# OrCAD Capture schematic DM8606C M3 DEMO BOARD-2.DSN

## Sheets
1 (1)MAIN_TP_FIBER: size A3; title: DM8606C M3 MODE DEMO BOARD; rev: 2.0; company: Davicom Semiconductor Inc; note: DM8606C_MAIN
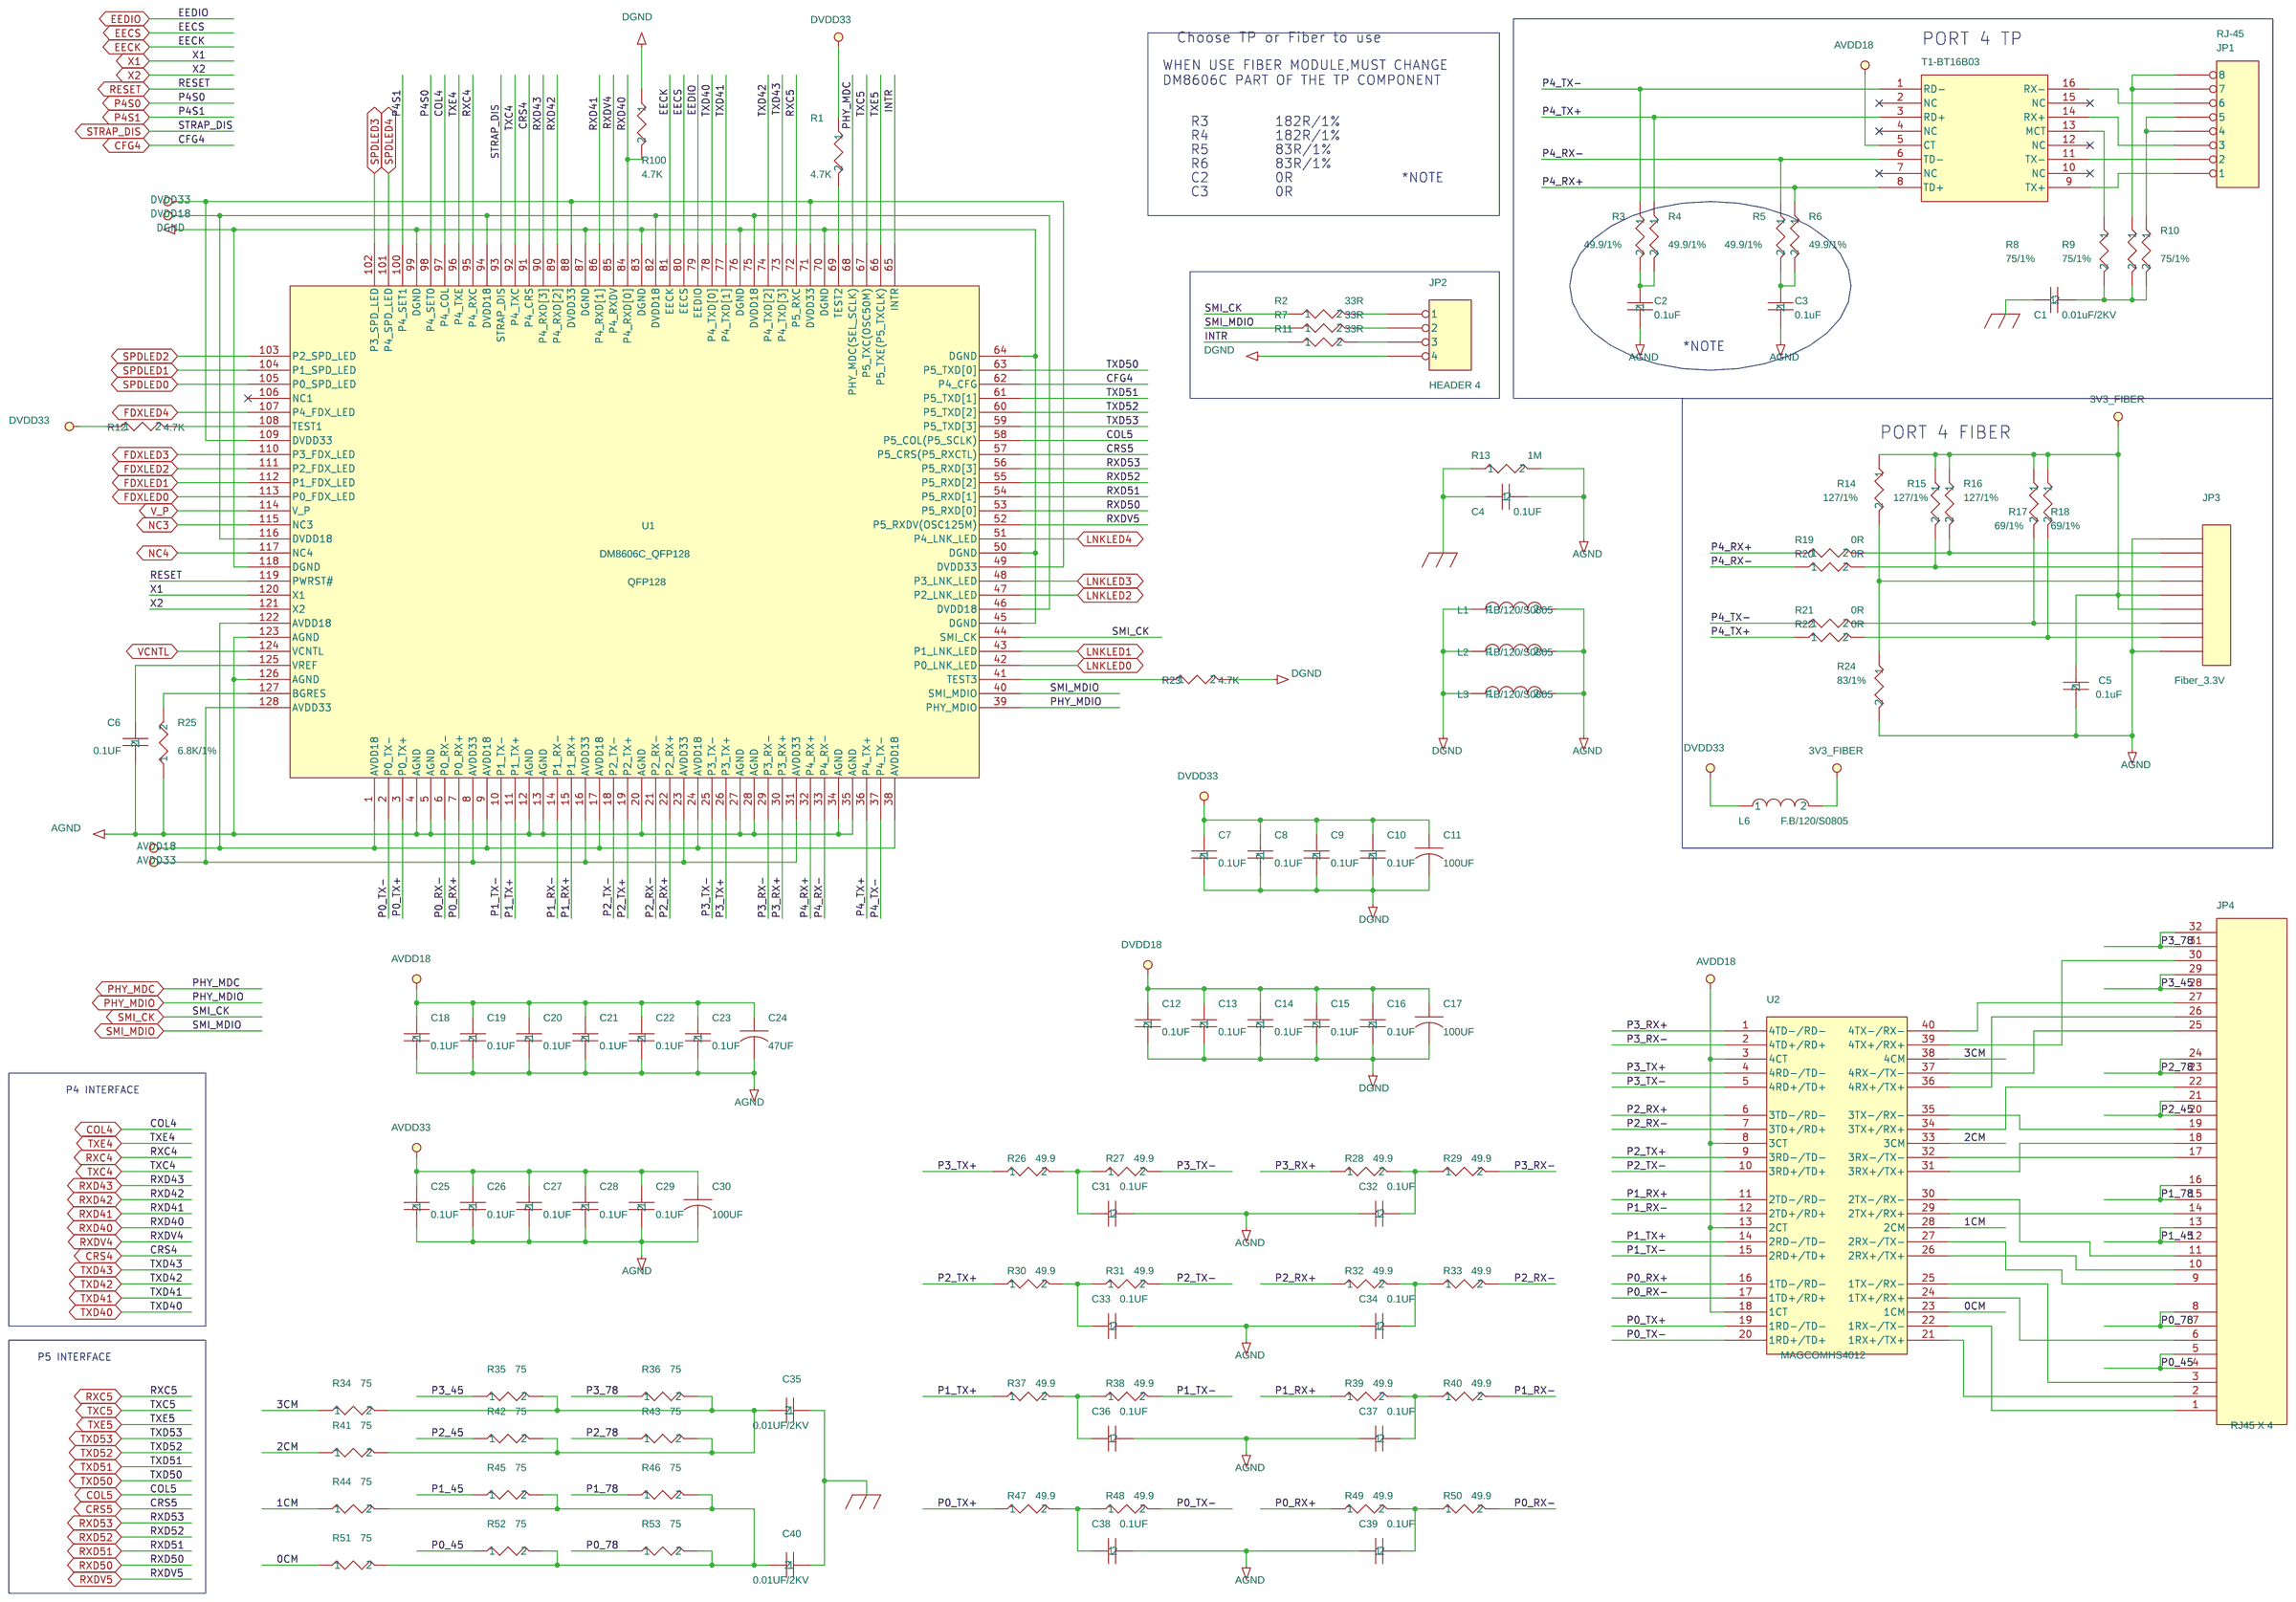
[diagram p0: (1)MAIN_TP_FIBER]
2 (2)RPOWER_STRAP_RST_XTAL_EPRROM: size A3; company: Davicom Semicondutor Inc; note: RPOWER_STRAP_RST_XTAL_EPRROM
3 (3)HISTORY: note: HISTORY
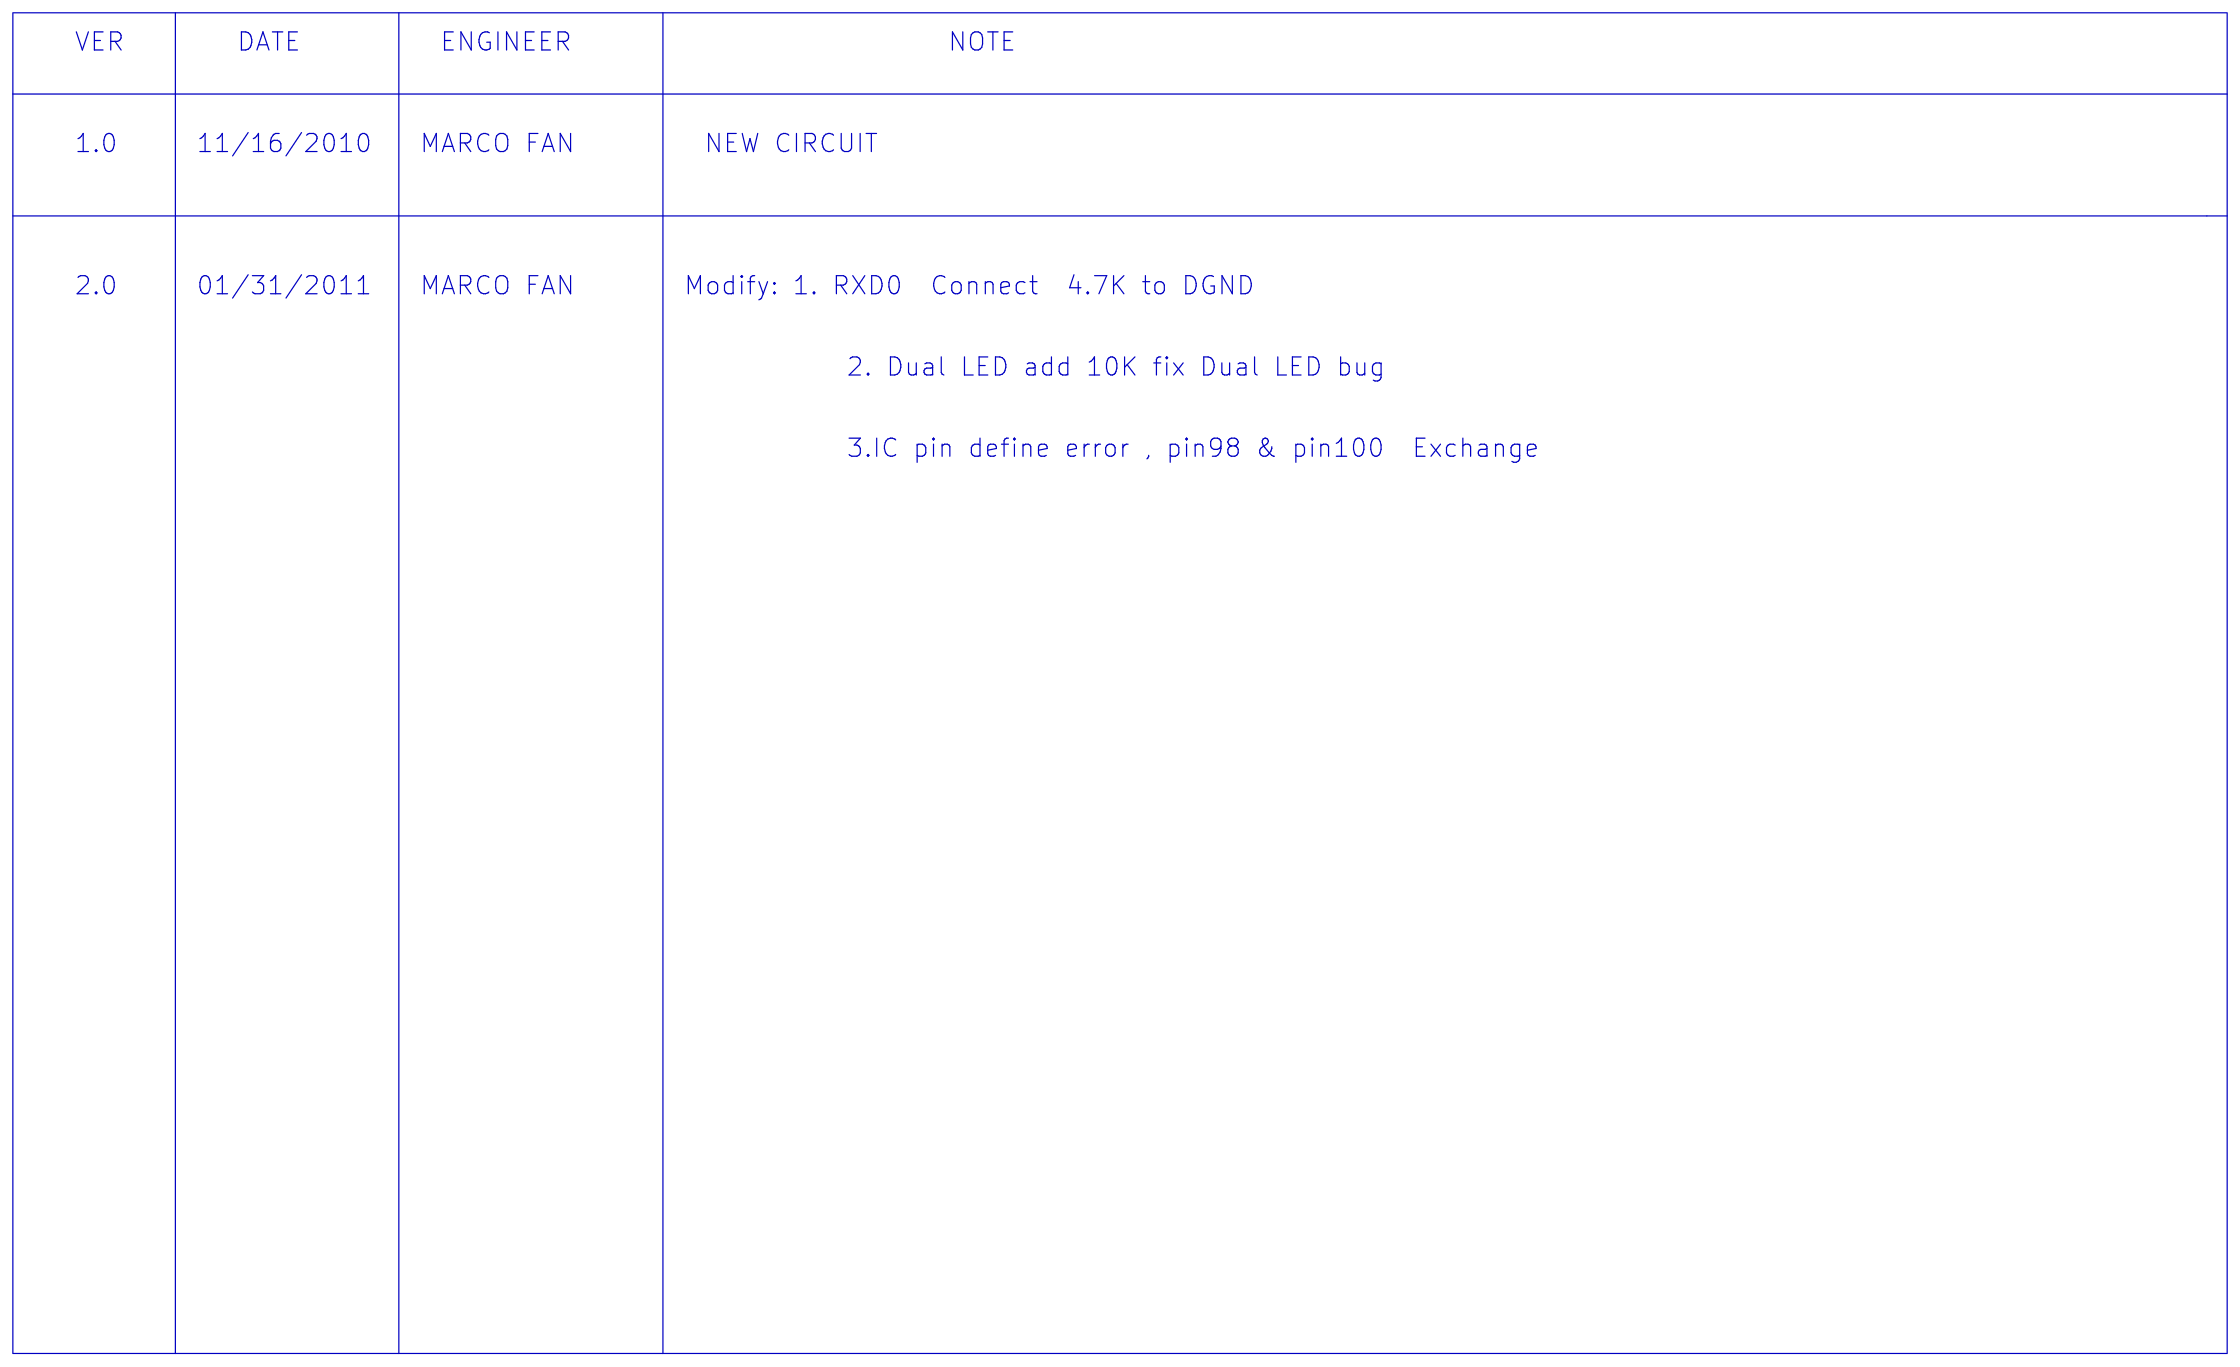
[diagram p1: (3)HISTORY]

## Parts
sheet (1)MAIN_TP_FIBER
C1  0.01uF/2KV  [CAP5MM]
C2  0.1uF  [C0603]
C3  0.1uF  [C0603]
C4  0.1UF  [C0603]
C5  0.1uF  [C0603]
C6  0.1UF  [C0603]
C7  0.1UF  [C0603]
C8  0.1UF  [C0603]
C9  0.1UF  [C0603]
C10  0.1UF  [C0603]
C11  100UF  [EC-MR05-2.5]
C12  0.1UF  [C0603]
C13  0.1UF  [C0603]
C14  0.1UF  [C0603]
C15  0.1UF  [C0603]
C16  0.1UF  [C0603]
C17  100UF  [EC-MR05-2.5]
C18  0.1UF  [C0603]
C19  0.1UF  [C0603]
C20  0.1UF  [C0603]
C21  0.1UF  [C0603]
C22  0.1UF  [C0603]
C23  0.1UF  [C0603]
C24  47UF  [EC-MR05-2.5]
C25  0.1UF  [C0603]
C26  0.1UF  [C0603]
C27  0.1UF  [C0603]
C28  0.1UF  [C0603]
C29  0.1UF  [C0603]
C30  100UF  [EC-MR05-2.5]
C31  0.1UF  [C0603]
C32  0.1UF  [C0603]
C33  0.1UF  [C0603]
C34  0.1UF  [C0603]
C35  0.01UF/2KV  [CAP5MM]
C36  0.1UF  [C0603]
C37  0.1UF  [C0603]
C38  0.1UF  [C0603]
C39  0.1UF  [C0603]
C40  0.01UF/2KV  [CAP5MM]
JP1  RJ-45  [RJ45]
JP2  HEADER 4  [CON4_SIP-2.54]
JP3  Fiber_3.3V  [FIBER]
JP4  RJ45 X 4  [YCLPTC1411-31_RJ45-4P]
L1  F.B/120/S0805  [R0805]
L2  F.B/120/S0805  [R0805]
L3  F.B/120/S0805  [R0805]
L6  F.B/120/S0805  [R0805]
R1  4.7K  [R0603]
R2  33R  [R0603]
R3  49.9/1%  [R0603]
R4  49.9/1%  [R0603]
R5  49.9/1%  [R0603]
R6  49.9/1%  [R0603]
R7  33R  [R0603]
R8  75/1%  [R0603]
R9  75/1%  [R0603]
R10  75/1%  [R0603]
R11  33R  [R0603]
R12  4.7K  [R0603]
R13  1M  [R0603]
R14  127/1%  [R0603]
R15  127/1%  [R0603]
R16  127/1%  [R0603]
R17  69/1%  [R0603]
R18  69/1%  [R0603]
R19  0R  [R0603]
R20  0R  [R0603]
R21  0R  [R0603]
R22  0R  [R0603]
R23  4.7K  [R0603]
R24  83/1%  [R0603]
R25  6.8K/1%  [R0603]
R26  49.9  [R0603]
R27  49.9  [R0603]
R28  49.9  [R0603]
R29  49.9  [R0603]
R30  49.9  [R0603]
R31  49.9  [R0603]
R32  49.9  [R0603]
R33  49.9  [R0603]
R34  75  [R0603]
R35  75  [R0603]
R36  75  [R0603]
R37  49.9  [R0603]
R38  49.9  [R0603]
R39  49.9  [R0603]
R40  49.9  [R0603]
R41  75  [R0603]
R42  75  [R0603]
R43  75  [R0603]
R44  75  [R0603]
R45  75  [R0603]
R46  75  [R0603]
R47  49.9  [R0603]
R48  49.9  [R0603]
R49  49.9  [R0603]
R50  49.9  [R0603]
R51  75  [R0603]
R52  75  [R0603]
R53  75  [R0603]
R100  4.7K
T1-BT16B03  MACOM9024  [PH163539]
U1  DM8606C_QFP128  [DM8606C-LQFP]
U2  MAGCOMHS4012  [MAGCOMHS4012_TR40-2916-1.27]
sheet (2)RPOWER_STRAP_RST_XTAL_EPRROM
C41  20P  [C0603]
C42  20P  [C0603]
C43  100UF/16V  [EC-MR05-2.5]
C44  100UF/10V  [EC-MR05-2.5]
C45  0.1UF  [C0603]
C46  0.1UF  [C0603]
C47  100UF/10V  [EC-MR05-2.5]
C48  0.1UF  [C0603]
C53  0.1uF  [C0603]
C54  100uF/10V  [EC-MR05-2.5]
C55  0.1uF  [C0603]
C56  100uF/10V  [EC-MR05-2.5]
C57  1uF  [C0603]
C58  0.1UF  [C0603]
C59  10UF/10V  [EC-MR05-2.5]
D2  DUAL LED  [2DIP-LED]
D3  DUAL LED  [2DIP-LED]
D4  DUAL LED  [2DIP-LED]
D5  DUAL LED  [2DIP-LED]
D6  DUAL LED  [2DIP-LED]
D7  DUAL LED  [2DIP-LED]
D8  DUAL LED  [2DIP-LED]
D9  DUAL LED  [2DIP-LED]
D10  DUAL LED  [2DIP-LED]
D11  DUAL LED  [2DIP-LED]
D12  DUAL LED  [2DIP-LED]
D13  DUAL LED  [2DIP-LED]
D14  DUAL LED  [2DIP-LED]
D15  LED  [2DIP-LED]
D16  LED  [2DIP-LED]
J1  CON3_0  [CON3_SIP3-2.54]
J2  CON3_0  [CON3_SIP3-2.54]
J3  CON3_0  [CON3_SIP3-2.54]
J4  CON3_0  [CON3_SIP3-2.54]
J5  CON3_0  [CON3_SIP3-2.54]
J6  CON3_0  [CON3_SIP3-2.54]
J7  CON3_0  [CON3_SIP3-2.54]
J8  CON3_0  [CON3_SIP3-2.54]
J9  JUMPER  [SIP2-2.54]
J10  CON3_0  [CON3_SIP3-2.54]
J11  CON3_0  [CON3_SIP3-2.54]
J12  CON3_0  [CON3_SIP3-2.54]
J13  CON3_0  [CON3_SIP3-2.54]
J14  CON3_0  [CON3_SIP3-2.54]
J15  CON3_0  [CON3_SIP3-2.54]
J16  CON3_0  [CON3_SIP3-2.54]
J17  CON3_0  [CON3_SIP3-2.54]
JP5  HEADER_16X2  [CON16X2-2.54A]
JP6  HEADER_16X2  [CON16X2-2.54A]
L4  F.B/120/S0805  [R0805]
L5  F.B/120/SO805  [R0805]
P1  DC-JACK  [DCJACK]
Q1  2SB1386  [SOT89]
R54  330  [R0603]
R55  330  [R0603]
R56  330  [R0603]
R57  10K  [R0603]
R58  330  [R0603]
R59  10K  [R0603]
R60  330  [R0603]
R61  10K  [R0603]
R62  330  [R0603]
R63  330  [R0603]
R64  10K  [R0603]
R65  330  [R0603]
R66  147  [R0603]
R67  10K  [R0603]
R68  330  [R0603]
R69  10K  [R0603]
R70  330  [R0603]
R71  10K  [R0603]
R72  330  [R0603]
R73  10K  [R0603]
R74  330  [R0603]
R75  10K  [R0603]
R76  10K  [R0603]
R77  10K  [R0603]
R78  330  [R0603]
R79  10K  [R0603]
R80  330  [R0603]
R81  10K  [R0603]
R82  330  [R0603]
R83  10K  [R0603]
R84  330  [R0603]
R85  10K  [R0603]
R86  NC/10K  [R0603]
R87  4.7K  [R0603]
R88  NC/10K  [R0603]
R90  4.7K  [R0603]
R92  4.7K/NC  [R0603]
R93  4.7K  [R0603]
R95  NC/4.7K  [R0603]
R96  NC/4.7K  [R0603]
R97  NC/4.7K  [R0603]
R98  NC/4.7K  [R0603]
R99  NC/4.7K  [R0603]
SW1  RESET_BUTTON  [SW-1102]
U3  RT9172  [SOT252]
U4  AP1117-1.8V  [SOT223]
U5  93C66/DIP8  [93C46]
U6  RESET_IC(AP1701DW)  [SOT23-213]
X1  25MHZ  [25MHZ/49US]

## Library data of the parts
C1 = CAP_NP_23: 1ST PART FIELD: CE
C2 C57 = CAP_NP_4
C3 C42 = CAP_NP_8
C4 = CAP_NP_13
C5 = CAP_NP_31
C6 = CAP_NP_28
C7 = CAP_NP_10
C8 = CAP_NP_33
C9 = CAP_NP_21
C10 C53 = CAP_NP_7
C11 C17 C30 = CAP
C12 = CAP_NP_32
C13 = CAP_NP_19
C14 C48 = CAP_NP_5
C15 = CAP_NP_30
C16 = CAP_NP_18
C18 = CAP_NP_12
C19 = CAP_NP_34
C20 = CAP_NP_24
C21 = CAP_NP_9
C22 = CAP_NP_17
C23 C46 = CAP_NP_1
C24 C47 C54 C56 = C
C25 = CAP_NP_14
C26 = CAP_NP_27
C27 C41 = CAP_NP_2
C28 C58 = CAP_NP
C29 = CAP_NP_25
C31 = CAP_NP_29
C32 = CAP_NP_16
C33 = CAP_NP_35
C34 = CAP_NP_20
C35 = CAP_NP_22: 1ST PART FIELD: C0603
C36 = CAP_NP_15
C37 C45 = CAP_NP_3
C38 = CAP_NP_26
C39 C55 = CAP_NP_6
C40 = CAP_NP_11: 1ST PART FIELD: C0603
JP1 = HEADER_8: 1ST PART FIELD: RJ8-45
JP2 = HEADER_8_0
JP3 = CON9
JP4 = RJ45X4_4
L1 = INDUCTOR_2
L2 L4 = INDUCTOR
L3 = INDUCTOR_3
L5 L6 = INDUCTOR_1
R1 R90 = RESISTOR_1
R2 = R_41
R3 = R_20
R4 = R_26
R5 = R_39
R6 = R_48
R7 = R_19
R8 = R_47
R9 = R_27
R10 R85 = R_15
R11 R93 = R_5
R12 R92 = RESISTOR
R13 = R_33
R14 R73 = R_6
R15 = R_25
R16 = R_22
R17 = R_32
R18 = R_21
R19 = R_43
R20 = R_18
R21 R64 = R_4
R22 = R_31
R23 R99 = RESISTOR_2
R24 R67 = R_8
R25 R95 = RESISTOR_3
R26 = R_24
R27 = R_46
R28 = R_30
R29 = R_38
R30 = R_35
R31 = R_37
R32 = R_44
R33 R79 = R_10
R34 = R_16
R35 = R_17
R36 R59 = R_14
R37 R69 = R_13
R38 R86 = R_9
R39 = R_49
R40 = R_42
R41 = R_34
R42 = R_36
R43 R66 = R_2
R44 = R_28
R45 R62 = R
R46 = R_40
R47 R88 = R_11
R48 R76 = R_7
R49 = R_45
R50 R58 = R_1
R51 = R_23
R52 R61 = R_12
R53 = R_29
R71 R100 = R_3
T1-BT16B03 = ETHERNET_TRANSFORMER_0
U1 = 9102A_15: 1ST PART FIELD: QFP128
U2 = MIM_9: 1ST PART FIELD: YCL0303
C43 = CAPACITOR_POL: 1ST PART FIELD: EC-MR05-2
C44 = CAPACITOR_POL_1: 1ST PART FIELD: EC-MR05-2
C59 = CAPACITOR_POL_2: 1ST PART FIELD: EC-MR05-2
D2-D14 = LED_0
D15 D16 = LED
J1-J8 J10-J17 = CON3_0
J9 = JUMPER
JP5 = HEADER_16X2_1
JP6 = HEADER_16X2
P1 = PJACK21_0: 3RD PART FIELD: DCIN; Package Type: 1; Part Number: 119211-005; Schematic Symbol: SIP3P
Q1 = BJT-PNP_0
R54-R57 R60 R63 R65 R68 R70 R72 R74 R77 R78 R80-R84 = resistor
R75 = RESISTOR_5
R87 = RESISTOR_6
R96 = RESISTOR_4
R97 = RESISTOR_7
R98 = RESISTOR_8
SW1 = SW_PUSHBUTTON: Package Type: 1
U3 = RT9172-25CM,TO-263_1
U4 = 1117-3_2.3
U5 = 9346_0
U6 = CON3_1
X1 = CRYSTAL

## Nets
3V3_FIBER: C5.1 JP3.5 JP3.6 L6.2 R14.1 R15.1 R16.1 R17.1 R18.1
5V: C43.1 C45.2 JP5.29 JP5.31 JP6.29 JP6.31 P1.1 U3.3(VIN)
AGND: C2.2 C3.2 C4.2 C5.2 C6.2 C18.2 C19.2 C20.2 C21.2 C22.2 C23.2 C24.2 C25.2 C26.2 C27.2 C28.2 C29.2 C30.2 C31.2 C32.1 C33.2 C34.1 C36.2 C37.1 C38.2 C39.1 C41.2 C42.2 C47.2 C48.2 C53.2 C54.2 C57.2 JP3.1 JP3.9 L1.2 L2.2 L3.2 R13.2 R24.2 R25.1 R66.2 U1.4(AGND) U1.5(AGND) U1.12(AGND) U1.13(AGND) U1.20(AGND) U1.27(AGND) U1.28(AGND) U1.34(AGND) U1.35(AGND) U1.123(AGND) U1.126(AGND)
AVDD18: C18.1 C19.1 C20.1 C21.1 C22.1 C23.1 C24.1 C53.1 C54.1 L5.1 Q1.C(COLLECTOR) R62.1 T1-BT16B03.5(CT) U1.1(AVDD18) U1.9(AVDD18) U1.17(AVDD18) U1.24(AVDD18) U1.38(AVDD18) U1.122(AVDD18) U2.3(4CT) U2.8(3CT) U2.13(2CT) U2.18(1CT) U4.2(OUT) U4.4(OUT)
AVDD33: C25.1 C26.1 C27.1 C28.1 C29.1 C30.1 C47.1 C48.1 L4.2 Q1.E(EMITTER) U1.8(AVDD33) U1.16(AVDD33) U1.23(AVDD33) U1.31(AVDD33) U1.128(AVDD33) U4.3(IN)
DGND: C7.2 C8.2 C9.2 C10.2 C11.2 C12.2 C13.2 C14.2 C15.2 C16.2 C17.2 C43.2 C44.2 C45.1 C46.2 C55.2 C56.2 C58.2 C59.2 J1.1 J2.1 J3.1 J4.1 J5.1 J6.1 J7.1 J8.1 J10.1 J11.1 J12.1 J13.1 J14.1 J15.1 J16.1 J17.1 JP2.4 JP5.23 JP5.25 JP5.27 JP6.23 JP6.25 JP6.27 L1.1 L2.1 L3.1 P1.2 P1.3 R23.2 R100.1 SW1.2 U1.45(DGND) U1.50(DGND) U1.64(DGND) U1.70(DGND) U1.76(DGND) U1.83(DGND) U1.87(DGND) U1.99(DGND) U1.118(DGND) U3.1(G) U5.5(GND) U6.1
DVDD18: C12.1 C13.1 C14.1 C15.1 C16.1 C17.1 C55.1 C56.1 L5.2 U1.46(DVDD18) U1.75(DVDD18) U1.82(DVDD18) U1.94(DVDD18) U1.116(DVDD18)
DVDD33: C7.1 C8.1 C9.1 C10.1 C11.1 C44.1 C46.1 C58.1 J1.3 J2.3 J3.3 J4.3 J5.3 J6.3 J7.3 J8.3 J10.3 J11.3 J12.3 J13.3 J14.3 J15.3 J16.3 J17.3 JP5.17 JP5.19 JP5.21 JP6.17 JP6.19 JP6.21 L4.1 L6.1 R1.1 R12.1 R54.2 R55.2 R76.2 R86.1 R88.1 R92.2 R95.2 R96.2 R97.2 R98.2 R99.2 U1.49(DVDD33) U1.71(DVDD33) U1.88(DVDD33) U1.109(DVDD33) U3.2(VOUT) U5.8(VCC) U6.3
GND_EARTH: C1.1 C4.1 C35.1 C40.1 R13.1
0CM: R51.1 U2.23(1CM)
1CM: R44.1 U2.28(2CM)
2CM: R41.1 U2.33(3CM)
3CM: R34.1 U2.38(4CM)
CFG4: R92.1 U1.62(P4_CFG)
COL4: JP5.14 U1.97(P4_COL)
COL5: JP6.14 U1.58(P5_COL(P5_SCLK))
CRS4: JP5.12 U1.91(P4_CRS)
CRS5: JP6.12 U1.57(P5_CRS(P5_RXCTL))
EECK: R98.1 U1.81(EECK) U5.2(SK)
EECS: J9.1 R97.1 U1.80(EECS)
EEDIO: R75.1 U1.79(EEDIO) U5.3(DI)
FDXLED0: D10.2(CATHODE) R77.1 U1.113(P0_FDX_LED)
FDXLED1: D11.2(CATHODE) R79.1 U1.112(P1_FDX_LED)
FDXLED2: D12.2(CATHODE) R81.1 U1.111(P2_FDX_LED)
FDXLED3: D13.2(CATHODE) R83.1 U1.110(P3_FDX_LED)
FDXLED4: D14.2(CATHODE) R85.1 U1.107(P4_FDX_LED)
INTR: R11.1 U1.65(INTR)
LNKLED0: D15.2(CATHODE) U1.42(P0_LNK_LED)
LNKLED1: D16.2(CATHODE) U1.43(P1_LNK_LED)
LNKLED2: D2.2(CATHODE) R57.1 U1.47(P2_LNK_LED)
LNKLED3: D3.2(CATHODE) R59.1 U1.48(P3_LNK_LED)
LNKLED4: D4.2(CATHODE) R61.1 U1.51(P4_LNK_LED)
NC3: R95.1 U1.115(NC3)
NC4: R96.1 U1.117(NC4)
P0_45: JP4.4 JP4.5 R52.1
P0_78: JP4.7 JP4.8 R53.1
P0_RX+: R49.1 U1.7(P0_RX+) U2.16(1TD-/RD-)
P0_RX-: R50.2 U1.6(P0_RX-) U2.17(1TD+/RD+)
P0_TX+: R47.1 U1.3(P0_TX+) U2.19(1RD-/TD-)
P0_TX-: R48.2 U1.2(P0_TX-) U2.20(1RD+/TD+)
P1_45: JP4.12 JP4.13 R45.1
P1_78: JP4.15 JP4.16 R46.1
P1_RX+: R39.1 U1.15(P1_RX+) U2.11(2TD-/RD-)
P1_RX-: R40.2 U1.14(P1_RX-) U2.12(2TD+/RD+)
P1_TX+: R37.1 U1.11(P1_TX+) U2.14(2RD-/TD-)
P1_TX-: R38.2 U1.10(P1_TX-) U2.15(2RD+/TD+)
P2_45: JP4.20 JP4.21 R42.1
P2_78: JP4.23 JP4.24 R43.1
P2_RX+: R32.1 U1.22(P2_RX+) U2.6(3TD-/RD-)
P2_RX-: R33.2 U1.21(P2_RX-) U2.7(3TD+/RD+)
P2_TX+: R30.1 U1.19(P2_TX+) U2.9(3RD-/TD-)
P2_TX-: R31.2 U1.18(P2_TX-) U2.10(3RD+/TD+)
P3_45: JP4.28 JP4.29 R35.1
P3_78: JP4.31 JP4.32 R36.1
P3_RX+: R28.1 U1.30(P3_RX+) U2.1(4TD-/RD-)
P3_RX-: R29.2 U1.29(P3_RX-) U2.2(4TD+/RD+)
P3_TX+: R26.1 U1.26(P3_TX+) U2.4(4RD-/TD-)
P3_TX-: R27.2 U1.25(P3_TX-) U2.5(4RD+/TD+)
P4_RX+: R6.1 R19.1 T1-BT16B03.8(TD+) U1.32(P4_RX+)
P4_RX-: R5.1 R20.1 T1-BT16B03.6(TD-) U1.33(P4_RX-)
P4_TX+: R4.1 R22.1 T1-BT16B03.3(RD+) U1.36(P4_TX+)
P4_TX-: R3.1 R21.1 T1-BT16B03.1(RD-) U1.37(P4_TX-)
P4S0: R87.1 U1.98(P4_SET0)
P4S1: R90.1 U1.100(P4_SET1)
PHY_MDC: JP5.1 JP6.1 U1.68(PHY_MDC(SEL_SCLK))
PHY_MDIO: JP5.2 JP6.2 U1.39(PHY_MDIO)
RESET: C59.1 JP5.15 JP6.15 R76.1 SW1.1 U1.119(PWRST#) U6.2
RXC4: JP5.22 U1.95(P4_RXC)
RXC5: JP6.22 U1.72(P5_RXC)
RXD40: JP5.24 R100.2 U1.84(P4_RXD[0])
RXD41: JP5.26 U1.86(P4_RXD[1])
RXD42: JP5.28 U1.89(P4_RXD[2])
RXD43: JP5.30 U1.90(P4_RXD[3])
RXD50: JP6.24 U1.53(P5_RXD[0])
RXD51: JP6.26 U1.54(P5_RXD[1])
RXD52: JP6.28 U1.55(P5_RXD[2])
RXD53: JP6.30 U1.56(P5_RXD[3])
RXDV4: JP5.3 U1.85(P4_RXDV)
RXDV5: JP6.3 U1.52(P5_RXDV(OSC125M))
SMI_CK: JP5.5 JP6.5 R2.1 U1.44(SMI_CK)
SMI_MDIO: JP5.32 JP6.32 R7.1 U1.40(SMI_MDIO)
SPDLED0: D5.2(CATHODE) R64.1 U1.105(P0_SPD_LED)
SPDLED1: D6.2(CATHODE) R67.1 U1.104(P1_SPD_LED)
SPDLED2: D7.2(CATHODE) R69.1 U1.103(P2_SPD_LED)
SPDLED3: D8.2(CATHODE) R71.1 U1.102(P3_SPD_LED)
SPDLED4: D9.2(CATHODE) R73.1 U1.101(P4_SPD_LED)
STRAP_DIS: R99.1 U1.93(STRAP_DIS)
TXC4: JP5.20 U1.92(P4_TXC)
TXC5: JP6.20 U1.67(P5_TXC(OSC50M))
TXD40: JP5.4 U1.78(P4_TXD[0])
TXD41: JP5.6 U1.77(P4_TXD[1])
TXD42: JP5.8 U1.74(P4_TXD[2])
TXD43: JP5.10 U1.73(P4_TXD[3])
TXD50: JP6.4 U1.63(P5_TXD[0])
TXD51: JP6.6 U1.61(P5_TXD[1])
TXD52: JP6.8 U1.60(P5_TXD[2])
TXD53: JP6.10 U1.59(P5_TXD[3])
TXE4: JP5.16 R86.2 U1.96(P4_TXE)
TXE5: JP6.16 R88.2 U1.66(P5_TXE(P5_TXCLK))
V_P: R93.1 U1.114(V_P)
VCNTL: C57.1 Q1.B(BASE) U1.124(VCNTL)
X1: C41.1 U1.120(X1) X1.1
X2: C42.1 U1.121(X2) X1.2
N17117535: R62.2 R66.1 U4.1(GND)
N17294018: C39.2 R49.2 R50.1
N17294160: C38.1 R47.2 R48.1
N17295044: C37.2 R39.2 R40.1
N17295054: C36.1 R37.2 R38.1
N17295154: C34.2 R32.2 R33.1
N17295164: C33.1 R30.2 R31.1
N17295271: C32.2 R28.2 R29.1
N17295281: C31.1 R26.2 R27.1
N17296004: C1.2 R8.2 R9.2 R10.2
N17296046: JP1.7 JP1.8 R9.1
N17296077: JP3.7 R17.2 R21.2
N17296402: JP3.2 R16.2 R19.2
N17296451: JP1.4 JP1.5 R10.1
N17296491: JP3.8 R18.2 R22.2
N17296604: C2.1 R3.2 R4.2
N17296639: R8.1 T1-BT16B03.13(MCT)
N17296762: C3.1 R5.2 R6.2
N17296870: JP1.1 T1-BT16B03.9(TX+)
N17296897: JP1.6 T1-BT16B03.16(RX-)
N17296958: JP3.3 R15.2 R20.2
N17297057: JP1.2 T1-BT16B03.11(TX-)
N17297449: JP1.3 T1-BT16B03.14(RX+)
N17297753: JP3.4 R14.2 R24.1
N17454346: C35.2 R34.2 R35.2 R36.2 R41.2 R42.2 R43.2
N17454466: C40.2 R44.2 R45.2 R46.2 R51.2 R52.2 R53.2
N17494448: D15.1(ANODE) R54.1
N17494482: D16.1(ANODE) R55.1
N17522727: JP4.1 U2.22(1RX-/TX-)
N17522814: JP4.2 U2.21(1RX+/TX+)
N17522903: JP4.3 U2.25(1TX-/RX-)
N17522990: JP4.6 U2.24(1TX+/RX+)
N17523079: JP4.9 U2.27(2RX-/TX-)
N17523175: JP4.10 U2.26(2RX+/TX+)
N17523264: JP4.11 U2.30(2TX-/RX-)
N17523360: JP4.14 U2.29(2TX+/RX+)
N17523442: JP4.17 U2.32(3RX-/TX-)
N17523530: JP4.18 U2.31(3RX+/TX+)
N17523619: JP4.19 U2.35(3TX-/RX-)
N17523706: JP4.22 U2.34(3TX+/RX+)
N17523878: JP4.25 U2.37(4RX-/TX-)
N17523965: JP4.26 U2.36(4RX+/TX+)
N17524052: JP4.27 U2.40(4TX-/RX-)
N17524139: JP4.30 U2.39(4TX+/RX+)
N17537725: R25.2 U1.127(BGRES)
N17538098: C6.1 U1.125(VREF)
N17539604: R12.2 U1.108(TEST1)
N17541811: R75.2 U5.4(DO)
N17542067: R1.2 U1.69(TEST2)
N17542486: R23.1 U1.41(TEST3)
N17546586: JP2.1 R2.2
N17546602: JP2.2 R7.2
N17546618: JP2.3 R11.2
N17577272: J15.2 R87.2
N17577286: J16.2 R90.2
N17577300: J17.2 R93.2
N17581844: D14.1(ANODE) R84.1
N17581858: D13.1(ANODE) R82.1
N17581872: D12.1(ANODE) R80.1
N17581886: D11.1(ANODE) R78.1
N17581900: D10.1(ANODE) R74.1
N17581914: D9.1(ANODE) R72.1
N17581928: D8.1(ANODE) R70.1
N17581942: D7.1(ANODE) R68.1
N17581956: D6.1(ANODE) R65.1
N17581984: D4.1(ANODE) R60.1
N17581998: D3.1(ANODE) R58.1
N17582075: D2.1(ANODE) R56.1
N17582089: J1.2 R56.2 R57.2
N17582103: J2.2 R58.2 R59.2
N17582117: J3.2 R60.2 R61.2
N17582131: J4.2 R63.2 R64.2
N17582145: J5.2 R65.2 R67.2
N17582159: J6.2 R68.2 R69.2
N17582173: J7.2 R70.2 R71.2
N17582187: J8.2 R72.2 R73.2
N17582201: J10.2 R74.2 R77.2
N17582215: J12.2 R80.2 R81.2
N17582229: J11.2 R78.2 R79.2
N17582243: J13.2 R82.2 R83.2
N17582257: J14.2 R84.2 R85.2
N17584057: J9.2 U5.1(CS)
N17588224: D5.1(ANODE) R63.1

Not connected (* = marked no-connect by the designer): JP5 7 9 11 13 18; JP6 7 9 11 13 18; T1-BT16B03 2(NC)* 4(NC)* 7(NC)* 10(NC)* 12(NC)* 15(NC)*; U1 106(NC1)*; U5 6(NC)* 7(NC)*

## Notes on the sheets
sheet 1
- Choose TP or Fiber to use
- PORT 4 TP
- WHEN USE FIBER MODULE,MUST CHANGE
  DM8606C PART OF THE TP COMPONENT
- R3
- 182R/1%
- R4
- 182R/1%
- R5
- R6
- 83R/1%
- 83R/1%
- C2
- 0R
- *NOTE
- C3
- 0R
- *NOTE
- PORT 4 FIBER
- P4 INTERFACE
- P5 INTERFACE
sheet 2
- LNKLED3,2
- J2 J1
- Default: 1  1
- Reserved
- Power 5V TO 3.3V
- LNKLED4
- J3
- Port 4 PHY TP mode in M3A or M3C mode
  1: Copper mode
  0: fiber mode
- SPDLED0
- When in M3B,Port4 in force mode
  0 : Half-duplex mode
  1: Full-duplex mode
- J4
- SPDLED1
- When in M3B,Port4 in force mode
  0 : 10M mode
  1 : 100M mode
- J5
- Power 3.3V TO 1.8V
- **
- SPDLED3,2
- Port 4 in M3B Mode
  SPDLED3 SPDLED2
    0      0     RevMII with TXC4 turbo clock
    0      1     RMII
    1      0     MII
    1      1     RevMII with TXC4 25MHz/2.5MHz clock
  Port 4 in M3C Mode
  SPDLED3 SPDLED2
     0       X     Reserved, do not use
     1       X     PHY_MII
- Choose U4 or Q1 to use
- J7 J6
- MULTIPLE FOOTPRINT
  PLACE SOT223&SOT89 PACKAGE AT
  SAME LOCATION
- ADJUSTABLE LDO CALCULATION
  Vout = Vref x ( 1 + R66 / R62)
  Vref = 1.25 V
  For fixed Vout LDO, R62 =
  open, R66 = 0 ohm
- SPDLED4
- When in M3B / M3C and Port4 in force mode
  0 : link OFF
  1 : link ON
- J8
- FDXLED0
- When Port5 in force mode
  0 : Half-duplex mode
  1 : Full-duplex mode
- J10
- FDXLED1
- When Port5 in force mode
  0 : 10M mode
  1 : 100M mode
- J11
- **
- FDXLED3,2
- Port 5 Mode
  FDXLED3 FDXLED2
    0      0    Reserved, do not use
     0      1    RMII
     1      0    MII
     1      1    RevMII
- J13 J12
- FDXLED4
- When Port5 in force mode
  0 : link OFF
  1 : link ON
- J14
- STRAP_DIS
- Strap pins disabled
  0: strap pins enabled
  1: no strap pin function
- RevMII USE
- P4 INTERFACE
- NC3
- Flow Control in PHY Register 4 bit 10
  0: bit value is ¨1〃
  1: bit value is ¨0〃
- P4 INTERFACE
- MII
  TXC
  TXE
  TXD3
  TXD2
  TXD1
  TXD0
  RXDV
  RXC
  RXER
  RXD3
  RXD2
  RXD1
  RXD0
  COL
  CRS
  MDC
  MDIO
- RMII
  TXE
  TXD1
  TXD0
  RXDV
  RXC
  RXD1
  RXD0
  CRS_DV
  MDC
  MDIO
- RevMII
  TXC
  RXC
  TXE
  TXD3
  TXD2
  TXD1
  TXD0
  RXDV
  RXD3
  RXD2
  RXD1
  RXD0
  CRS
  RXER
- EXTERNAL MII
  RXC
  TXC
  RXDV
  RXD3
  RXD2
  RXD1
  RXD0
  TXE
  TXD3
  TXD2
  TXD1
  TXD0
  CRS
  COL
  RXER
- **
- EECS
- Port 5 link/duplex/speed mode in MII/RMII
  0: force mode
  1: PHY_MDC/PHY_MDIO polling mode
- P5 INTERFACE
- EECK
- When in M3B , Port 4 link/duplex/speed mode in MII/RMII
  0: force mode
  1: PHY_MDC/PHY_MDIO polling mode
  When in M3B , Port 4 link/duplex/speed mode in RevMII mode,
  Port 4 always in force mode
- Port 4 operation mode
  CFG4     P4_SET1     P4_SET0
     0       0        0    use internal PHY(M3A)
     0       0        1    MII/RMII/RevMII(M3B)
     1       X        X    TP MII (M3C)
- J16
- J15
- DGND
- V_P
- J17
- Default: 0
- Reserved
- P5 INTERFACE
sheet 3
- VER
- DATE
- ENGINEER
- NOTE
- 1.0
- 11/16/2010
- MARCO FAN
- NEW CIRCUIT
- 2.0
- 01/31/2011
- MARCO FAN
- Modify: 1. RXD0  Connect  4.7K to DGND
- 2. Dual LED add 10K fix Dual LED bug
- 3.IC pin define error , pin98 & pin100  Exchange
